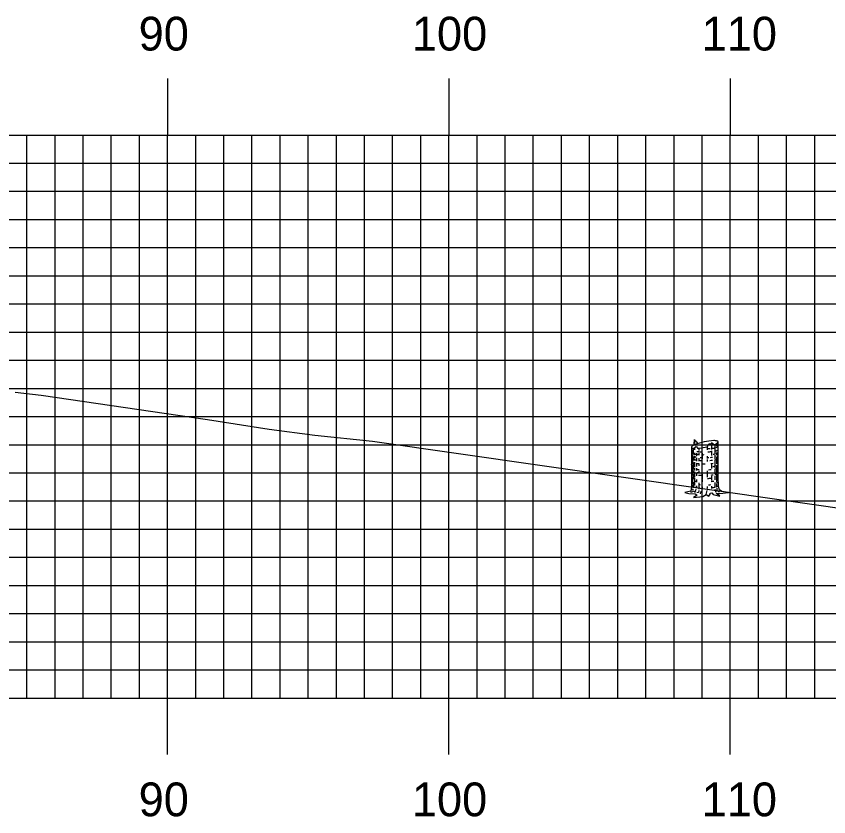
# Model space of a CAD drawing. Extents: x 852087 to 852430, y 366898 to 367118.
# Drawn here: x 852337.15 to 852366.03, y 367003.94 to 367032.38 of the extents above; entities that cross this region are included whole.
import ezdxf

# ---------------------------------------------------------------- set-up
doc = ezdxf.new("R2010")
doc.units = 0
for name, color, linetype in [('H_V ANNOTATION', 7, 'Continuous'), ('MAJOR', 7, 'Continuous'), ('MINOR', 7, 'Continuous'), ('S_Roadway_Centerline', 7, 'Continuous'), ('S_Trees_Decid_NonPay', 7, 'Continuous')]:
    doc.layers.add(name, color=color, linetype=linetype)

msp = doc.modelspace()

# ---------------------------------------------------------------- linework, layer by layer
at = {"layer": 'MAJOR'}
for p, q in [((852342.531, 367030.165), (852342.531, 367028.161)), ((852352.531, 367030.165), (852352.531, 367028.161)), ((852362.531, 367030.165), (852362.531, 367028.161)), ((852112.531, 367028.161), (852392.531, 367028.161)), ((852112.531, 367028.161), (852392.531, 367028.161)), ((852342.531, 367008.161), (852342.531, 367028.161)), ((852352.531, 367008.161), (852352.531, 367028.161)), ((852362.531, 367008.161), (852362.531, 367028.161)), ((852112.531, 367023.161), (852392.531, 367023.161)), ((852112.531, 367018.161), (852392.531, 367018.161)), ((852112.531, 367013.161), (852392.531, 367013.161)), ((852112.531, 367008.161), (852392.531, 367008.161)), ((852112.531, 367008.161), (852392.531, 367008.161)), ((852342.531, 367006.157), (852342.531, 367008.161)), ((852352.531, 367006.157), (852352.531, 367008.161)), ((852362.531, 367006.157), (852362.531, 367008.161))]:
    msp.add_line(p, q, dxfattribs=at)
at = {"layer": 'MINOR'}
for p, q in [((852337.531, 367008.161), (852337.531, 367028.161)), ((852338.531, 367008.161), (852338.531, 367028.161)), ((852339.531, 367008.161), (852339.531, 367028.161)), ((852340.531, 367008.161), (852340.531, 367028.161)), ((852341.531, 367008.161), (852341.531, 367028.161)), ((852343.531, 367008.161), (852343.531, 367028.161)), ((852344.531, 367008.161), (852344.531, 367028.161)), ((852345.531, 367008.161), (852345.531, 367028.161)), ((852346.531, 367008.161), (852346.531, 367028.161)), ((852347.531, 367008.161), (852347.531, 367028.161)), ((852348.531, 367008.161), (852348.531, 367028.161)), ((852349.531, 367008.161), (852349.531, 367028.161)), ((852350.531, 367008.161), (852350.531, 367028.161)), ((852351.531, 367008.161), (852351.531, 367028.161)), ((852353.531, 367008.161), (852353.531, 367028.161)), ((852354.531, 367008.161), (852354.531, 367028.161)), ((852355.531, 367008.161), (852355.531, 367028.161)), ((852356.531, 367008.161), (852356.531, 367028.161)), ((852357.531, 367008.161), (852357.531, 367028.161)), ((852358.531, 367008.161), (852358.531, 367028.161)), ((852359.531, 367008.161), (852359.531, 367028.161)), ((852360.531, 367008.161), (852360.531, 367028.161)), ((852361.531, 367008.161), (852361.531, 367028.161)), ((852363.531, 367008.161), (852363.531, 367028.161)), ((852364.531, 367008.161), (852364.531, 367028.161)), ((852365.531, 367008.161), (852365.531, 367028.161)), ((852112.531, 367027.161), (852392.531, 367027.161)), ((852112.531, 367026.161), (852392.531, 367026.161)), ((852112.531, 367025.161), (852392.531, 367025.161)), ((852112.531, 367024.161), (852392.531, 367024.161)), ((852112.531, 367022.161), (852392.531, 367022.161)), ((852112.531, 367021.161), (852392.531, 367021.161)), ((852112.531, 367020.161), (852392.531, 367020.161)), ((852112.531, 367019.161), (852392.531, 367019.161)), ((852112.531, 367017.161), (852392.531, 367017.161)), ((852112.531, 367016.161), (852392.531, 367016.161)), ((852112.531, 367015.161), (852392.531, 367015.161)), ((852112.531, 367014.161), (852392.531, 367014.161)), ((852112.531, 367012.161), (852392.531, 367012.161)), ((852112.531, 367011.161), (852392.531, 367011.161)), ((852112.531, 367010.161), (852392.531, 367010.161)), ((852112.531, 367009.161), (852392.531, 367009.161))]:
    msp.add_line(p, q, dxfattribs=at)
at = {"layer": 'S_Roadway_Centerline'}
msp.add_lwpolyline([(852337.113, 367019.027), (852338.043, 367018.914), (852343.951, 367018.056), (852346.148, 367017.712), (852347.762, 367017.504), (852349.813, 367017.28), (852358.822, 367015.994), (852367.486, 367014.752), (852368.716, 367014.728), (852372.915, 367014.517), (852373.687, 367014.538), (852378.806, 367014.779), (852380.034, 367014.842), (852387.67, 367015.125), (852392.531, 367015.348)], dxfattribs=at)
at = {"layer": 'S_Trees_Decid_NonPay'}
for p, q in [((852361.188, 367016.962), (852361.188, 367016.88)), ((852361.215, 367017.032), (852361.215, 367016.815)), ((852361.257, 367017.027), (852361.257, 367016.975)), ((852361.415, 367017.038), (852361.415, 367016.959)), ((852361.712, 367017.09), (852361.712, 367016.983)), ((852361.859, 367017.136), (852361.859, 367016.988)), ((852361.978, 367017.119), (852361.978, 367016.818)), ((852362.046, 367017.206), (852362.046, 367017.111)), ((852361.188, 367016.811), (852361.188, 367016.681)), ((852361.188, 367016.658), (852361.188, 367016.477)), ((852361.215, 367016.746), (852361.215, 367016.594)), ((852361.257, 367016.872), (852361.257, 367016.79)), ((852361.257, 367016.755), (852361.257, 367016.681)), ((852361.328, 367016.854), (852361.328, 367016.767)), ((852361.328, 367016.697), (852361.328, 367016.576)), ((852361.415, 367016.872), (852361.415, 367016.788)), ((852361.415, 367016.677), (852361.415, 367016.576)), ((852361.532, 367016.854), (852361.532, 367016.654)), ((852361.712, 367016.755), (852361.712, 367016.668)), ((852361.859, 367016.94), (852361.859, 367016.771)), ((852361.978, 367016.79), (852361.978, 367016.658)), ((852362.046, 367016.885), (852362.046, 367016.802)), ((852362.046, 367016.732), (852362.046, 367016.481)), ((852361.188, 367016.429), (852361.188, 367016.183)), ((852361.215, 367016.489), (852361.215, 367016.411)), ((852361.215, 367016.384), (852361.215, 367016.277)), ((852361.257, 367016.654), (852361.257, 367016.594)), ((852361.257, 367016.541), (852361.257, 367016.36)), ((852361.328, 367016.5), (852361.328, 367016.386)), ((852361.415, 367016.491), (852361.415, 367016.415)), ((852361.712, 367016.633), (852361.712, 367016.563)), ((852361.859, 367016.465), (852361.859, 367016.316)), ((852361.978, 367016.624), (852361.978, 367016.343)), ((852362.046, 367016.398), (852362.046, 367016.168)), ((852361.188, 367016.164), (852361.188, 367016.069)), ((852361.215, 367016.242), (852361.215, 367016.141)), ((852361.215, 367016.116), (852361.215, 367015.933)), ((852361.257, 367016.328), (852361.257, 367016.246)), ((852361.257, 367016.192), (852361.257, 367016.022)), ((852361.328, 367016.324), (852361.328, 367016.242)), ((852361.328, 367016.156), (852361.328, 367016.059)), ((852361.415, 367016.23), (852361.415, 367016.133)), ((852361.532, 367016.116), (852361.532, 367015.929)), ((852361.712, 367016.23), (852361.712, 367016.007)), ((852361.978, 367016.273), (852361.978, 367016.129)), ((852362.046, 367016.098), (852362.046, 367015.937)), ((852361.186, 367016.016), (852361.187, 367015.756)), ((852361.215, 367015.83), (852361.215, 367015.639)), ((852361.257, 367015.988), (852361.257, 367015.709)), ((852361.328, 367015.929), (852361.328, 367015.83)), ((852361.415, 367015.808), (852361.415, 367015.584)), ((852361.532, 367015.898), (852361.532, 367015.845)), ((852361.859, 367016.047), (852361.859, 367015.894)), ((852361.978, 367016.059), (852361.978, 367015.917)), ((852361.978, 367015.816), (852361.978, 367015.635)), ((852362.046, 367015.921), (852362.046, 367015.816)), ((852361.217, 367015.591), (852361.182, 367015.54)), ((852361.188, 367015.717), (852361.188, 367015.643)), ((852361.257, 367015.656), (852361.257, 367015.631)), ((852361.328, 367015.701), (852361.328, 367015.643)), ((852361.532, 367015.669), (852361.532, 367015.579)), ((852361.672, 367015.388), (852361.707, 367015.534)), ((852361.712, 367015.674), (852361.712, 367015.608)), ((852361.859, 367015.682), (852361.859, 367015.604)), ((852361.979, 367015.575), (852362.02, 367015.479)), ((852362.046, 367015.779), (852362.046, 367015.655)), ((852361.135, 367015.47), (852361.202, 367015.501))]:
    msp.add_line(p, q, dxfattribs=at)
for points in [[(852361.147, 367017.07), (852361.147, 367015.658), (852361.124, 367015.509), (852360.921, 367015.466), (852361.061, 367015.431), (852361.279, 367015.412), (852361.349, 367015.369), (852361.227, 367015.28), (852361.559, 367015.324), (852361.672, 367015.388), (852361.765, 367015.328), (852361.82, 367015.406), (852361.812, 367015.443), (852361.874, 367015.445), (852361.925, 367015.388), (852362.158, 367015.336), (852362.03, 367015.425), (852362.162, 367015.427), (852362.471, 367015.464), (852362.232, 367015.495), (852362.154, 367015.553), (852362.115, 367015.674), (852362.098, 367016.028), (852362.098, 367017.261)], [(852361.242, 367017.15), (852361.246, 367017.245), (852361.26, 367017.218), (852361.26, 367017.339), (852361.281, 367017.276), (852361.295, 367017.309), (852361.312, 367017.253), (852361.328, 367017.27), (852361.347, 367017.261), (852361.366, 367017.194)], [(852361.734, 367017.095), (852361.742, 367017.162), (852361.767, 367017.167), (852361.775, 367017.202), (852361.806, 367017.187), (852361.82, 367017.202), (852361.845, 367017.179), (852361.868, 367017.187), (852361.88, 367017.236), (852361.888, 367017.193), (852361.919, 367017.202), (852361.922, 367017.15)], [(852361.264, 367017.026), (852361.281, 367017.088), (852361.303, 367017.076), (852361.334, 367017.111), (852361.368, 367017.033)], [(852361.186, 367015.517), (852361.265, 367015.501), (852361.281, 367015.458)], [(852361.265, 367015.501), (852361.308, 367015.536), (852361.316, 367015.584)], [(852361.412, 367015.536), (852361.406, 367015.466), (852361.343, 367015.454)], [(852361.524, 367015.53), (852361.524, 367015.493), (852361.473, 367015.462), (852361.456, 367015.412)], [(852362.049, 367015.612), (852362.057, 367015.536), (852362.135, 367015.486)]]:
    msp.add_lwpolyline(points, dxfattribs=at)
for centre, radius, start, end in [((852362.117, 367014.803), 2.507, 101.8277, 109.7098), ((852362.117, 367014.803), 2.507, 93.9457, 101.8277), ((852361.967, 367016.983), 0.322, 71.8277, 93.9457), ((852362.038, 367017.2), 0.0935, 60.604, 71.8277), ((852362.017, 367017.301), 0.0935, 311.8277, 323.0514), ((852362.067, 367017.252), 0.0336, 41.8277, 60.604), ((852362.065, 367017.265), 0.0336, 323.0514, 341.8277), ((852362.075, 367017.259), 0.0237, 27.8832, 41.8277), ((852362.08, 367017.261), 0.0179, 11.8277, 27.8832), ((852362.08, 367017.261), 0.0179, 355.7722, 11.8277), ((852362.074, 367017.262), 0.0237, 341.8277, 355.7722), ((852361.171, 367017.069), 0.0237, 161.8277, 175.7722), ((852361.165, 367017.07), 0.0179, 175.7722, 191.8277), ((852361.165, 367017.07), 0.0179, 191.8277, 207.8832), ((852361.18, 367017.066), 0.0336, 143.0514, 161.8277), ((852361.167, 367017.001), 0.0191, 173.8872, 180), ((852361.167, 367017.001), 0.0191, 180, 196.0515), ((852361.173, 367017.002), 0.0252, 196.0515, 210), ((852361.17, 367017.073), 0.0237, 207.8832, 221.8277), ((852361.182, 367017.008), 0.0356, 210, 228.7494), ((852361.177, 367017.079), 0.0336, 221.8277, 240.604), ((852361.228, 367017.03), 0.0935, 131.8277, 143.0514), ((852361.223, 367017.055), 0.0984, 228.7494, 240), ((852361.207, 367017.131), 0.0935, 240.604, 251.8277), ((852361.38, 367016.86), 0.322, 109.7098, 131.8277), ((852361.337, 367017.252), 0.326, 240, 248.0494), ((852361.278, 367017.348), 0.322, 251.8277, 267.5521), ((852361.127, 367019.528), 2.507, 275.4987, 281.8277), ((852361.127, 367019.528), 2.507, 281.8277, 284.0013), ((852361.623, 367019.375), 2.356, 272.1614, 274.76), ((852361.623, 367019.375), 2.356, 276.7201, 278.1032), ((852361.127, 367019.528), 2.507, 288.4719, 289.7098), ((852361.909, 367017.365), 0.326, 278.1032, 282.1964), ((852361.864, 367017.471), 0.322, 289.7098, 311.8277), ((852361.909, 367017.252), 0.326, 282.1964, 299.0901), ((852361.909, 367017.365), 0.326, 291.6757, 300), ((852362.023, 367017.168), 0.0984, 300, 311.2506), ((852362.064, 367017.121), 0.0356, 311.2506, 330), ((852362.073, 367017.116), 0.0252, 330, 343.9485), ((852362.079, 367017.114), 0.0191, 0, 16.0515), ((852362.079, 367017.114), 0.0191, 343.9485, 0), ((852361.167, 367016.9), 0.0191, 173.8872, 180), ((852361.167, 367016.9), 0.0191, 180, 196.0515), ((852361.173, 367016.902), 0.0252, 196.0515, 210), ((852361.167, 367016.797), 0.0191, 173.8872, 180), ((852361.167, 367016.797), 0.0191, 180, 196.0515), ((852361.167, 367016.692), 0.0191, 173.8872, 180), ((852361.167, 367016.692), 0.0191, 180, 196.0515), ((852361.173, 367016.694), 0.0252, 196.0515, 210), ((852361.182, 367016.907), 0.0356, 210, 228.7494), ((852361.182, 367016.699), 0.0356, 210, 228.7494), ((852361.223, 367016.954), 0.0984, 228.7494, 240), ((852361.223, 367016.746), 0.0984, 228.7494, 240), ((852361.337, 367017.151), 0.326, 240, 248.0494), ((852361.337, 367016.943), 0.326, 240, 248.0494), ((852361.337, 367017.048), 0.326, 255.9618, 261.8968), ((852361.337, 367017.151), 0.326, 260.9146, 261.8968), ((852361.623, 367019.161), 2.356, 261.8968, 264.9353), ((852361.623, 367019.058), 2.356, 261.8968, 262.6162), ((852361.623, 367019.262), 2.356, 263.2266, 266.8519), ((852361.623, 367019.058), 2.356, 266.0259, 267.8019), ((852361.623, 367019.161), 2.356, 267.8019, 269.1881), ((852361.623, 367019.058), 2.356, 272.1614, 273.4964), ((852361.623, 367019.262), 2.356, 272.6327, 275.758), ((852361.623, 367019.058), 2.356, 275.0054, 276.6587), ((852361.623, 367019.161), 2.356, 277.4481, 278.1032), ((852361.909, 367017.151), 0.326, 278.1032, 289.5833), ((852361.909, 367017.048), 0.326, 282.1964, 288.3169), ((852361.909, 367017.151), 0.326, 296.4281, 300), ((852361.909, 367017.048), 0.326, 296.757, 300), ((852362.023, 367016.954), 0.0984, 300, 311.2506), ((852362.023, 367016.851), 0.0984, 300, 311.2506), ((852362.064, 367016.907), 0.0356, 311.2506, 330), ((852362.064, 367016.804), 0.0356, 311.2506, 330), ((852362.073, 367016.902), 0.0252, 330, 343.9485), ((852362.073, 367016.799), 0.0252, 330, 343.9485), ((852362.079, 367016.9), 0.0191, 0, 16.0515), ((852362.079, 367016.9), 0.0191, 343.9485, 0), ((852362.079, 367016.797), 0.0191, 0, 16.0515), ((852362.079, 367016.797), 0.0191, 343.9485, 0), ((852361.166, 367016.462), 0.0191, 173.8872, 180), ((852361.166, 367016.462), 0.0191, 180, 196.0515), ((852361.167, 367016.577), 0.0191, 173.8872, 180), ((852361.167, 367016.577), 0.0191, 180, 196.0515), ((852361.173, 367016.579), 0.0252, 196.0515, 210), ((852361.172, 367016.464), 0.0252, 196.0515, 210), ((852361.181, 367016.469), 0.0356, 210, 228.7494), ((852361.182, 367016.584), 0.0356, 210, 228.7494), ((852361.222, 367016.517), 0.0984, 228.7494, 240), ((852361.223, 367016.631), 0.0984, 228.7494, 240), ((852361.336, 367016.714), 0.326, 240, 242.9942), ((852361.337, 367016.828), 0.326, 240, 255.9618), ((852361.336, 367016.714), 0.326, 248.1902, 256.0964), ((852361.337, 367016.943), 0.326, 255.9618, 261.8968), ((852361.623, 367018.953), 2.356, 261.8968, 262.8132), ((852361.623, 367018.838), 2.356, 262.8132, 264.9353), ((852361.623, 367018.953), 2.356, 264.9353, 266.9933), ((852361.623, 367018.838), 2.356, 267.586, 270), ((852361.623, 367018.838), 2.356, 270, 270.4422), ((852361.623, 367018.953), 2.356, 274.3638, 276.7318), ((852361.623, 367018.838), 2.356, 275.2089, 277.3412), ((852361.622, 367018.724), 2.356, 277.1385, 278.1032), ((852361.908, 367016.714), 0.326, 278.1032, 282.3301), ((852361.909, 367016.943), 0.326, 282.1964, 294.8455), ((852361.908, 367016.714), 0.326, 292.1344, 300), ((852361.909, 367016.828), 0.326, 294.8455, 300), ((852362.022, 367016.517), 0.0984, 300, 311.2506), ((852362.023, 367016.631), 0.0984, 300, 311.2506), ((852362.064, 367016.469), 0.0356, 311.2506, 330), ((852362.064, 367016.584), 0.0356, 311.2506, 330), ((852362.073, 367016.579), 0.0252, 330, 343.9485), ((852362.073, 367016.464), 0.0252, 330, 343.9485), ((852362.079, 367016.462), 0.0191, 0, 16.0515), ((852362.079, 367016.462), 0.0191, 343.9485, 0), ((852362.079, 367016.577), 0.0191, 0, 16.0515), ((852362.079, 367016.577), 0.0191, 343.9485, 0), ((852361.167, 367016.257), 0.0191, 173.8872, 180), ((852361.167, 367016.257), 0.0191, 180, 196.0515), ((852361.173, 367016.259), 0.0252, 196.0515, 210), ((852361.167, 367016.167), 0.0191, 173.8872, 180), ((852361.169, 367016.362), 0.0191, 173.8872, 180), ((852361.169, 367016.362), 0.0191, 180, 196.0515), ((852361.175, 367016.364), 0.0252, 196.0515, 210), ((852361.182, 367016.264), 0.0356, 210, 228.7494), ((852361.184, 367016.369), 0.0356, 210, 228.7494), ((852361.223, 367016.312), 0.0984, 228.7494, 240), ((852361.225, 367016.416), 0.0984, 228.7494, 240), ((852361.337, 367016.509), 0.326, 240, 242.8475), ((852361.339, 367016.614), 0.326, 240, 247.5951), ((852361.337, 367016.509), 0.326, 248.0494, 255.9618), ((852361.625, 367018.624), 2.356, 262.7545, 265.0266), ((852361.623, 367018.519), 2.356, 263.572, 264.9353), ((852361.623, 367018.428), 2.356, 264.7274, 267.8019), ((852361.623, 367018.519), 2.356, 270.9946, 272.1614), ((852361.625, 367018.624), 2.356, 273.1471, 275.6557), ((852361.623, 367018.428), 2.356, 275.5135, 277.4157), ((852361.912, 367016.614), 0.326, 283.0921, 300), ((852361.909, 367016.418), 0.326, 286.0817, 298.061), ((852361.909, 367016.509), 0.326, 294.8455, 300), ((852362.023, 367016.312), 0.0984, 300, 311.2506), ((852362.064, 367016.264), 0.0356, 311.2506, 330), ((852362.073, 367016.259), 0.0252, 330, 343.9485), ((852362.079, 367016.257), 0.0191, 0, 16.0515), ((852362.079, 367016.257), 0.0191, 343.9485, 0), ((852362.082, 367016.362), 0.0191, 0, 16.0515), ((852361.171, 367015.938), 0.0191, 173.8872, 180), ((852361.171, 367015.938), 0.0191, 180, 196.0515), ((852361.177, 367015.94), 0.0252, 196.0515, 210), ((852361.186, 367015.945), 0.0356, 210, 228.7494), ((852361.227, 367015.993), 0.0984, 228.7494, 240), ((852361.346, 367016.079), 0.326, 240, 246.3456), ((852361.337, 367016.305), 0.326, 248.0494, 255.9618), ((852361.341, 367016.19), 0.326, 255.2259, 261.8968), ((852361.627, 367018.2), 2.356, 261.8968, 262.7137), ((852361.623, 367018.315), 2.356, 272.531, 275.758), ((852361.627, 367018.2), 2.356, 275.5148, 277.7774), ((852361.913, 367016.19), 0.326, 294.0625, 300), ((852361.918, 367016.079), 0.326, 298.0903, 300), ((852362.027, 367015.993), 0.0984, 300, 311.2506), ((852362.032, 367015.882), 0.0984, 300, 311.2506), ((852362.068, 367015.945), 0.0356, 311.2506, 330), ((852362.073, 367015.835), 0.0356, 311.2506, 330), ((852362.077, 367015.94), 0.0252, 330, 343.9485), ((852362.083, 367015.938), 0.0191, 0, 16.0515), ((852362.083, 367015.938), 0.0191, 343.9485, 0), ((852362.082, 367015.83), 0.0252, 330, 343.9485), ((852362.088, 367015.828), 0.0191, 0, 16.0515), ((852362.088, 367015.828), 0.0191, 343.9485, 0), ((852361.181, 367015.718), 0.0191, 173.8872, 180), ((852361.181, 367015.718), 0.0191, 180, 196.0515), ((852361.187, 367015.719), 0.0252, 196.0515, 210), ((852361.196, 367015.724), 0.0356, 210, 228.7494), ((852361.237, 367015.772), 0.0984, 228.7494, 240), ((852361.351, 367015.969), 0.326, 245.2906, 261.8968), ((852361.637, 367017.979), 2.356, 261.8968, 262.4597), ((852361.632, 367018.089), 2.356, 264.7171, 265.8136), ((852361.637, 367017.979), 2.356, 264.5833, 265.4449), ((852361.632, 367018.089), 2.356, 273.1842, 275.0911), ((852361.637, 367017.979), 2.356, 276.4667, 278.1032), ((852361.924, 367015.969), 0.326, 278.1032, 279.6166), ((852361.924, 367015.969), 0.326, 292.0839, 300), ((852362.037, 367015.772), 0.0984, 300, 311.2506), ((852362.079, 367015.724), 0.0356, 311.2506, 330), ((852362.088, 367015.719), 0.0252, 330, 343.9485), ((852362.094, 367015.718), 0.0191, 0, 16.0515), ((852362.094, 367015.718), 0.0191, 343.9485, 0)]:
    msp.add_arc(centre, radius, start, end, dxfattribs=at)

# ---------------------------------------------------------------- texts
at = {"layer": 'H_V ANNOTATION'}
for s, p in [('90', (852341.503, 367031.161)), ('100', (852351.214, 367031.161)), ('110', (852361.514, 367031.161)), ('90', (852341.503, 367003.961)), ('100', (852351.214, 367003.961)), ('110', (852361.514, 367003.961))]:
    msp.add_text(s, height=1.2, dxfattribs=at).set_placement(p)

doc.saveas('drawing.dxf')
